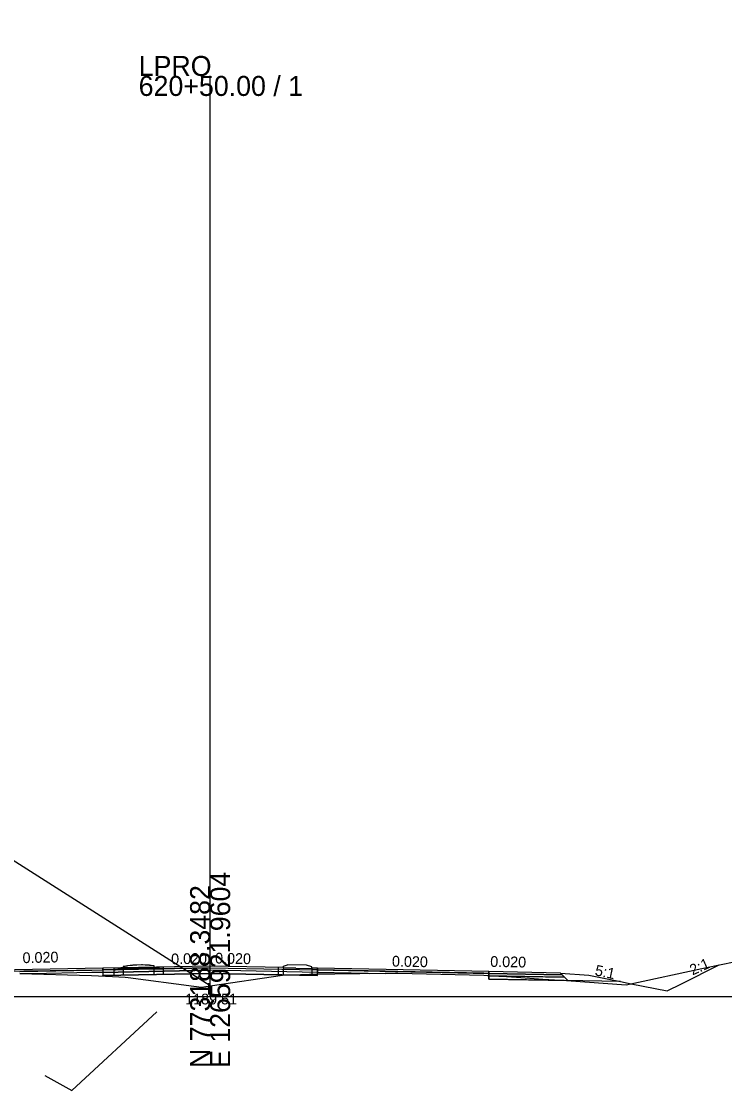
# Model space of a CAD drawing. Extents: x -3833 to 1267678, y -522 to 773248.
# Drawn here: x 3123.6 to 3222, y 1486.8 to 1636.6 of the extents above; entities that cross this region are included whole.
import ezdxf

# ---------------------------------------------------------------- set-up
doc = ezdxf.new("R2010")
doc.units = 0
for name, color, linetype in [('Exist Cross Section Cell', 7, 'Continuous'), ('Exist XS Center Line Elevation Label', 7, 'Continuous'), ('Exist XS Ground Line', 7, 'Continuous'), ('Prop CMT DNC', 7, 'Continuous'), ('Prop CMT Pvmt Course 1', 7, 'Continuous'), ('Prop CMT Pvmt Course 2', 7, 'Continuous'), ('Prop CMT Pvmt Course 3', 7, 'Continuous'), ('Prop CMT Pvmt Course 4', 7, 'Continuous'), ('Prop CMT Shld Paved Course 1', 7, 'Continuous'), ('Prop CMT Shld Paved Course 2', 7, 'Continuous'), ('Prop CMT Shld Paved Course 4', 7, 'Continuous'), ('Prop CMT Slope Grass', 7, 'Continuous'), ('Prop CMT Subgrade Earthwork', 7, 'Continuous'), ('Prop Conc Curb and Gutter', 7, 'Continuous'), ('Prop Conc Island Cover', 7, 'Continuous'), ('Prop Corridor Mesh Bottom', 7, 'Continuous'), ('Prop XS Ditch Slope Text', 7, 'Continuous'), ('Prop XS Finish Grade', 7, 'Continuous'), ('Prop XS SE Text', 7, 'Continuous'), ('Scratch_Level_1', 7, 'Continuous'), ('Scratch_Level_5', 7, 'Continuous')]:
    doc.layers.add(name, color=color, linetype=linetype)

msp = doc.modelspace()

# ---------------------------------------------------------------- linework, layer by layer
at = {"layer": 'Exist Cross Section Cell'}
for p, q in [((3150, 1500), (3150, 1628.93)), ((3000, 1500), (3150, 1500)), ((3150, 1500), (3300, 1500))]:
    msp.add_line(p, q, dxfattribs=at)
at = {"layer": 'Exist XS Ground Line'}
for p, q in [((3219.46, 1504.07), (3230.76, 1506.43)), ((3208.23, 1501.64), (3219.46, 1504.07)), ((3123.36, 1503.25), (3133.42, 1502.93)), ((3133.42, 1502.93), (3136.33, 1502.83)), ((3136.33, 1502.83), (3138.13, 1502.7)), ((3138.13, 1502.7), (3138.55, 1502.67)), ((3138.55, 1502.67), (3147.7, 1501.47)), ((3150, 1501.51), (3160.12, 1503)), ((3160.12, 1503), (3163.88, 1503.14)), ((3163.88, 1503.14), (3174.5, 1503.28)), ((3174.5, 1503.28), (3175.34, 1503.28)), ((3175.34, 1503.28), (3176.26, 1503.26)), ((3176.26, 1503.26), (3188.3, 1502.98)), ((3188.3, 1502.98), (3189.31, 1502.92)), ((3189.31, 1502.92), (3191.48, 1502.8)), ((3191.48, 1502.8), (3192.86, 1502.7)), ((3192.86, 1502.7), (3196.56, 1502.46)), ((3196.56, 1502.46), (3199.86, 1502.25)), ((3199.86, 1502.25), (3208.23, 1501.64)), ((3147.7, 1501.47), (3148.8, 1501.3)), ((3148.8, 1501.3), (3149.41, 1501.43)), ((3149.41, 1501.43), (3150, 1501.51))]:
    msp.add_line(p, q, dxfattribs=at)
at = {"layer": 'Prop CMT Pvmt Course 1'}
for p, q in [((3135, 1503.98), (3105, 1503.38)), ((3111.07, 1503.42), (3135, 1503.73)), ((3135, 1503.73), (3135, 1503.98)), ((3135, 1503.73), (3135, 1503.73)), ((3136.56, 1504), (3136.56, 1504.01)), ((3136.56, 1504.01), (3136.59, 1504.01)), ((3136.56, 1503.76), (3136.56, 1504)), ((3136.59, 1503.76), (3136.56, 1503.76)), ((3136.59, 1504.01), (3136.59, 1504.01)), ((3136.59, 1504.01), (3136.75, 1504.01)), ((3136.75, 1503.76), (3136.59, 1503.76)), ((3136.59, 1503.76), (3136.59, 1503.76)), ((3136.75, 1504.01), (3136.75, 1504.01)), ((3136.75, 1504.01), (3136.76, 1504.01)), ((3136.76, 1503.76), (3136.75, 1503.76)), ((3136.75, 1503.76), (3136.75, 1503.76)), ((3136.76, 1504.01), (3137.07, 1504.02)), ((3137.07, 1503.77), (3136.76, 1503.76)), ((3137.07, 1504.02), (3137.27, 1504.02)), ((3137.27, 1503.77), (3137.07, 1503.77)), ((3137.27, 1504.02), (3137.52, 1504.02)), ((3137.52, 1503.77), (3137.27, 1503.77)), ((3137.52, 1504.02), (3137.82, 1504.02)), ((3137.82, 1503.77), (3137.52, 1503.77)), ((3137.82, 1504.02), (3137.82, 1503.88)), ((3137.82, 1503.88), (3137.82, 1503.77)), ((3142.19, 1503.98), (3142.19, 1504.13)), ((3142.19, 1504.13), (3142.52, 1504.13)), ((3142.19, 1503.88), (3142.19, 1503.98)), ((3142.52, 1503.88), (3142.19, 1503.88)), ((3142.52, 1504.13), (3142.65, 1504.14)), ((3142.65, 1503.89), (3142.52, 1503.88)), ((3142.65, 1504.14), (3142.9, 1504.14)), ((3142.9, 1503.89), (3142.65, 1503.89)), ((3142.9, 1504.14), (3143.34, 1504.15)), ((3143.34, 1503.9), (3142.9, 1503.89)), ((3143.34, 1504.15), (3143.38, 1504.15)), ((3143.38, 1503.9), (3143.34, 1503.9)), ((3143.38, 1504.15), (3143.44, 1504.15)), ((3143.44, 1503.9), (3143.38, 1503.9)), ((3143.44, 1504.15), (3143.44, 1504.13)), ((3143.44, 1504.13), (3143.44, 1503.9)), ((3159.5, 1504.09), (3159.5, 1504.09)), ((3159.5, 1504.09), (3159.5, 1503.84)), ((3159.5, 1503.84), (3159.5, 1503.84)), ((3159.5, 1503.84), (3159.5, 1503.84)), ((3160.25, 1503.85), (3160.25, 1504.1)), ((3160.25, 1503.85), (3160.25, 1503.85)), ((3165, 1503.98), (3164.25, 1503.99)), ((3164.25, 1503.99), (3164.25, 1503.74)), ((3164.25, 1503.74), (3164.25, 1503.74)), ((3189, 1503.5), (3165, 1503.98)), ((3165, 1503.98), (3165, 1503.73)), ((3165, 1503.73), (3165, 1503.98)), ((3165, 1503.98), (3165, 1503.98)), ((3165, 1503.73), (3165, 1503.73)), ((3165, 1503.73), (3189, 1503.25)), ((3165, 1503.73), (3165, 1503.73)), ((3165, 1503.73), (3165, 1503.73)), ((3189, 1503.25), (3189, 1503.5)), ((3189, 1503.5), (3189, 1503.5)), ((3189, 1503.25), (3189, 1503.25)), ((3189, 1503.25), (3189, 1503.25))]:
    msp.add_line(p, q, dxfattribs=at)
at = {"layer": 'Prop CMT Pvmt Course 2'}
for p, q in [((3150, 1504.03), (3135, 1503.73)), ((3135, 1503.73), (3135, 1503.73)), ((3135, 1503.73), (3135, 1503.4)), ((3135, 1503.39), (3150, 1503.7)), ((3136.56, 1503.75), (3136.56, 1503.76)), ((3136.56, 1503.76), (3136.59, 1503.76)), ((3136.56, 1503.51), (3136.56, 1503.75)), ((3136.59, 1503.76), (3136.59, 1503.76)), ((3136.59, 1503.76), (3136.75, 1503.76)), ((3136.75, 1503.76), (3136.75, 1503.76)), ((3136.75, 1503.76), (3136.76, 1503.76)), ((3136.76, 1503.76), (3137.07, 1503.77)), ((3137.07, 1503.77), (3137.27, 1503.77)), ((3137.27, 1503.77), (3137.52, 1503.77)), ((3137.52, 1503.77), (3137.82, 1503.77)), ((3137.82, 1503.77), (3137.82, 1503.63)), ((3137.82, 1503.63), (3137.82, 1503.52)), ((3142.19, 1503.73), (3142.19, 1503.88)), ((3142.19, 1503.88), (3142.52, 1503.88)), ((3142.19, 1503.63), (3142.19, 1503.73)), ((3142.52, 1503.88), (3142.65, 1503.89)), ((3142.65, 1503.89), (3142.9, 1503.89)), ((3142.9, 1503.89), (3143.34, 1503.9)), ((3143.34, 1503.9), (3143.38, 1503.9)), ((3143.38, 1503.9), (3143.44, 1503.9)), ((3143.44, 1503.9), (3143.44, 1503.88)), ((3143.44, 1503.88), (3143.44, 1503.65)), ((3159.5, 1503.84), (3159.5, 1503.84)), ((3159.5, 1503.84), (3159.5, 1503.59)), ((3159.5, 1503.59), (3159.5, 1503.59)), ((3159.5, 1503.59), (3159.5, 1503.59)), ((3160.25, 1503.6), (3160.25, 1503.85)), ((3160.25, 1503.6), (3160.25, 1503.6)), ((3165, 1503.73), (3164.25, 1503.74)), ((3164.25, 1503.74), (3164.25, 1503.49)), ((3164.25, 1503.49), (3164.25, 1503.49)), ((3165, 1503.39), (3165, 1503.73)), ((3165, 1503.73), (3165, 1503.73)), ((3165, 1503.48), (3165, 1503.73)), ((3165, 1503.73), (3165, 1503.73)), ((3165, 1503.48), (3165, 1503.48)), ((3165, 1503.48), (3165, 1503.48)), ((3135, 1503.4), (3135, 1503.4)), ((3135, 1503.4), (3135, 1503.39)), ((3135, 1503.39), (3135, 1503.39)), ((3135, 1503.39), (3135, 1503.39)), ((3165, 1503.39), (3165, 1503.39)), ((3165, 1503.39), (3165, 1503.39)), ((3165, 1503.39), (3165, 1503.39))]:
    msp.add_line(p, q, dxfattribs=at)
at = {"layer": 'Prop CMT Pvmt Course 3'}
for p, q in [((3136.56, 1503.5), (3136.56, 1503.51)), ((3136.56, 1503.13), (3136.56, 1503.5)), ((3137.82, 1503.52), (3137.82, 1503.31)), ((3142.19, 1503.41), (3142.19, 1503.63)), ((3143.44, 1503.65), (3143.44, 1503.62)), ((3143.44, 1503.62), (3143.44, 1503.27)), ((3159.5, 1503.59), (3159.5, 1503.59)), ((3159.5, 1503.59), (3159.5, 1503.05)), ((3160.25, 1503.03), (3160.25, 1503.6)), ((3164.25, 1503.49), (3164.25, 1502.95)), ((3165, 1502.94), (3165, 1503.48)), ((3165, 1503.48), (3165, 1503.48)), ((3137.82, 1503.31), (3137.82, 1503.15)), ((3142.19, 1503.25), (3142.19, 1503.41)), ((3159.5, 1503.21), (3159.5, 1503.21)), ((3159.5, 1503.21), (3159.5, 1503.21)), ((3160.25, 1503.23), (3160.25, 1503.23)), ((3164.25, 1503.12), (3164.25, 1503.12)), ((3174.47, 1503.2), (3164.99, 1503.39)), ((3165, 1503.1), (3165, 1503.1)), ((3165, 1503.1), (3165, 1503.1))]:
    msp.add_line(p, q, dxfattribs=at)
at = {"layer": 'Prop CMT Pvmt Course 4'}
for p, q in [((3150, 1503.7), (3135, 1503.39)), ((3165, 1503.39), (3150, 1503.7)), ((3135, 1503.39), (3135, 1503.4)), ((3135, 1503.4), (3135, 1502.88)), ((3135, 1503.39), (3135, 1503.39)), ((3135, 1503.39), (3135, 1503.39)), ((3135, 1502.94), (3150.01, 1503.24)), ((3136.56, 1503.12), (3136.56, 1503.13)), ((3136.56, 1502.97), (3136.56, 1503.12)), ((3137.82, 1503.15), (3137.82, 1502.99)), ((3142.19, 1503.08), (3142.19, 1503.25)), ((3143.44, 1503.27), (3143.44, 1503.23)), ((3143.44, 1503.23), (3143.44, 1503.11)), ((3150, 1503.24), (3165, 1502.94)), ((3159.5, 1503.21), (3159.5, 1503.21)), ((3165, 1502.94), (3165, 1503.39)), ((3165, 1503.39), (3165, 1503.39)), ((3165, 1503.39), (3165, 1503.39)), ((3165, 1502.94), (3165, 1503.1)), ((3165, 1503.1), (3165, 1503.1))]:
    msp.add_line(p, q, dxfattribs=at)
at = {"layer": 'Prop CMT Shld Paved Course 1'}
for p, q in [((3150, 1504.28), (3135, 1503.98)), ((3135, 1503.73), (3150, 1504.03)), ((3135, 1503.98), (3135, 1503.98)), ((3135, 1503.98), (3135, 1503.73)), ((3135, 1503.73), (3135, 1503.73)), ((3135, 1503.73), (3135, 1503.73)), ((3160.25, 1504.07), (3150, 1504.28)), ((3150, 1504.03), (3165, 1503.73)), ((3165, 1503.98), (3164.25, 1503.99)), ((3165, 1503.73), (3165, 1503.98)), ((3165, 1503.98), (3165, 1503.98)), ((3165, 1503.73), (3165, 1503.73)), ((3165, 1503.73), (3165, 1503.73)), ((3189, 1503.5), (3189, 1503.25)), ((3199, 1503.3), (3189, 1503.5)), ((3189, 1503.25), (3199.26, 1503.04)), ((3199.26, 1503.04), (3199, 1503.3))]:
    msp.add_line(p, q, dxfattribs=at)
at = {"layer": 'Prop CMT Shld Paved Course 2'}
for p, q in [((3123.35, 1503.49), (3133.43, 1503.7)), ((3133.43, 1503.7), (3135, 1503.73)), ((3133.43, 1503.7), (3133.43, 1503.7)), ((3135, 1503.73), (3135, 1503.73)), ((3135, 1503.73), (3135, 1503.39)), ((3174.48, 1503.54), (3165, 1503.73)), ((3165, 1503.73), (3165, 1503.39)), ((3175.34, 1503.52), (3174.48, 1503.54)), ((3174.48, 1503.54), (3174.48, 1503.54)), ((3176.26, 1503.5), (3175.34, 1503.52)), ((3175.34, 1503.52), (3175.34, 1503.52)), ((3175.34, 1503.52), (3175.34, 1503.52)), ((3188.29, 1503.26), (3176.26, 1503.5)), ((3176.26, 1503.5), (3176.26, 1503.5)), ((3125.01, 1503.19), (3123.35, 1503.25)), ((3133.43, 1503.36), (3125.01, 1503.19)), ((3125.01, 1503.19), (3125.01, 1503.19)), ((3135, 1503.39), (3133.43, 1503.36)), ((3133.43, 1503.36), (3133.43, 1503.36)), ((3135, 1503.39), (3135, 1503.39)), ((3135, 1503.39), (3135, 1503.39)), ((3165, 1503.39), (3165, 1503.39)), ((3165, 1503.39), (3165, 1503.39)), ((3165, 1503.39), (3172.33, 1503.25)), ((3172.33, 1503.25), (3174.48, 1503.28)), ((3174.48, 1503.28), (3174.48, 1503.28)), ((3174.48, 1503.28), (3175.34, 1503.28)), ((3175.34, 1503.28), (3175.34, 1503.28)), ((3175.34, 1503.28), (3175.34, 1503.28)), ((3175.34, 1503.28), (3176.26, 1503.26)), ((3176.26, 1503.26), (3176.26, 1503.26)), ((3176.26, 1503.26), (3188.29, 1502.98)), ((3189, 1503.25), (3188.29, 1503.26)), ((3188.29, 1503.26), (3188.29, 1503.26)), ((3188.29, 1502.98), (3188.29, 1502.98)), ((3188.29, 1502.98), (3189, 1502.94)), ((3189, 1502.94), (3189, 1503.25)), ((3189, 1503.25), (3189, 1503.25)), ((3189, 1503.25), (3189, 1502.92)), ((3199.26, 1503.04), (3189, 1503.25)), ((3189, 1502.94), (3189, 1502.94)), ((3189, 1502.94), (3189, 1502.94)), ((3189, 1502.92), (3199.59, 1502.71)), ((3199.59, 1502.71), (3199.26, 1503.04))]:
    msp.add_line(p, q, dxfattribs=at)
at = {"layer": 'Prop CMT Shld Paved Course 4'}
for p, q in [((3189, 1502.92), (3189, 1502.46)), ((3199.09, 1502.72), (3189, 1502.92)), ((3189, 1502.46), (3200.06, 1502.24)), ((3199.59, 1502.71), (3199.09, 1502.72)), ((3200.06, 1502.24), (3199.59, 1502.71))]:
    msp.add_line(p, q, dxfattribs=at)
at = {"layer": 'Prop CMT Slope Grass'}
for p, q in [((3199, 1503.3), (3203, 1502.98)), ((3203, 1502.98), (3207.44, 1502.09))]:
    msp.add_line(p, q, dxfattribs=at)
at = {"layer": 'Prop CMT Subgrade Earthwork'}
for p, q in [((3150, 1503.24), (3135, 1502.94)), ((3135, 1502.88), (3135, 1502.94)), ((3165, 1502.94), (3150, 1503.24)), ((3165, 1502.94), (3165, 1503.15)), ((3189, 1502.46), (3189, 1502.94)), ((3207.44, 1502.09), (3189, 1502.46))]:
    msp.add_line(p, q, dxfattribs=at)
at = {"layer": 'Prop Conc Curb and Gutter'}
for p, q in [((3137.83, 1504.1), (3137.82, 1504.02)), ((3137.82, 1503.95), (3137.82, 1504.02)), ((3137.82, 1503.9), (3137.82, 1503.95)), ((3138.15, 1503.9), (3137.82, 1503.9)), ((3137.84, 1504.19), (3137.83, 1504.1)), ((3138.08, 1504.23), (3137.84, 1504.19)), ((3138.2, 1504.26), (3138.08, 1504.23)), ((3138.2, 1503.9), (3138.15, 1503.9)), ((3138.24, 1504.26), (3138.2, 1504.26)), ((3138.25, 1503.9), (3138.2, 1503.9)), ((3138.25, 1504.26), (3138.24, 1504.26)), ((3138.32, 1504.27), (3138.25, 1504.26)), ((3138.34, 1503.9), (3138.25, 1503.9)), ((3138.25, 1503.9), (3138.25, 1503.9)), ((3138.35, 1504.28), (3138.32, 1504.27)), ((3138.35, 1503.9), (3138.34, 1503.9)), ((3138.44, 1504.29), (3138.35, 1504.28)), ((3138.48, 1503.9), (3138.35, 1503.9)), ((3138.49, 1504.3), (3138.44, 1504.29)), ((3138.49, 1503.9), (3138.48, 1503.9)), ((3138.8, 1504.33), (3138.49, 1504.3)), ((3138.98, 1503.91), (3138.49, 1503.9)), ((3139.08, 1504.37), (3138.8, 1504.33)), ((3139.08, 1503.91), (3138.98, 1503.91)), ((3139.19, 1504.38), (3139.08, 1504.37)), ((3139.32, 1503.91), (3139.08, 1503.91)), ((3139.38, 1504.39), (3139.19, 1504.38)), ((3139.38, 1503.92), (3139.32, 1503.91)), ((3139.41, 1504.4), (3139.38, 1504.39)), ((3139.45, 1503.92), (3139.38, 1503.92)), ((3139.47, 1504.4), (3139.41, 1504.4)), ((3139.47, 1503.92), (3139.45, 1503.92)), ((3139.72, 1504.41), (3139.47, 1504.4)), ((3139.68, 1503.93), (3139.47, 1503.92)), ((3140.39, 1503.94), (3139.68, 1503.93)), ((3140.39, 1504.43), (3139.72, 1504.41)), ((3140.41, 1504.43), (3140.39, 1504.43)), ((3140.39, 1504.43), (3140.39, 1504.43)), ((3140.41, 1503.94), (3140.39, 1503.94)), ((3140.39, 1503.94), (3140.39, 1503.94)), ((3140.55, 1504.43), (3140.41, 1504.43)), ((3140.52, 1503.95), (3140.41, 1503.94)), ((3140.89, 1503.96), (3140.52, 1503.95)), ((3140.89, 1504.42), (3140.55, 1504.43)), ((3141.1, 1504.4), (3140.89, 1504.42)), ((3140.97, 1503.96), (3140.89, 1503.96)), ((3141.35, 1503.97), (3140.97, 1503.96)), ((3141.35, 1504.39), (3141.1, 1504.4)), ((3141.43, 1504.38), (3141.35, 1504.39)), ((3141.37, 1503.98), (3141.35, 1503.97)), ((3141.48, 1503.98), (3141.37, 1503.98)), ((3141.48, 1504.38), (3141.43, 1504.38)), ((3141.5, 1504.38), (3141.48, 1504.38)), ((3141.51, 1503.98), (3141.48, 1503.98)), ((3141.48, 1503.98), (3141.48, 1503.98)), ((3141.51, 1504.37), (3141.5, 1504.38)), ((3141.69, 1504.36), (3141.51, 1504.37)), ((3141.53, 1503.98), (3141.51, 1503.98)), ((3141.76, 1503.99), (3141.53, 1503.98)), ((3141.76, 1504.35), (3141.69, 1504.36)), ((3142.17, 1504.29), (3141.76, 1504.35)), ((3141.8, 1503.99), (3141.76, 1503.99)), ((3142.19, 1504), (3141.8, 1503.99)), ((3142.18, 1504.2), (3142.17, 1504.29)), ((3142.19, 1504.13), (3142.18, 1504.2)), ((3142.19, 1504.13), (3142.19, 1504.05)), ((3142.19, 1504.05), (3142.19, 1504)), ((3160.25, 1504.1), (3160.26, 1504.27)), ((3160.25, 1503.98), (3160.25, 1504.1)), ((3160.25, 1504.1), (3160.25, 1504.1)), ((3162.01, 1503.98), (3160.25, 1503.98)), ((3160.25, 1503.98), (3160.25, 1503.98)), ((3160.26, 1504.27), (3160.84, 1504.46)), ((3160.26, 1504.27), (3160.26, 1504.27)), ((3163.49, 1504.41), (3160.84, 1504.46)), ((3162.01, 1503.98), (3162.01, 1503.98)), ((3162.01, 1503.98), (3162.01, 1503.98)), ((3162.01, 1503.98), (3164.25, 1503.93)), ((3164.24, 1504.16), (3163.49, 1504.41)), ((3163.49, 1504.41), (3163.49, 1504.41)), ((3164.25, 1503.93), (3164.24, 1504.16)), ((3164.24, 1504.16), (3164.24, 1504.16)), ((3164.25, 1503.99), (3164.25, 1503.99)), ((3164.25, 1503.99), (3164.25, 1503.99)), ((3164.25, 1503.99), (3164.25, 1503.99)), ((3164.25, 1503.87), (3164.25, 1503.87)), ((3164.25, 1503.87), (3164.25, 1503.87))]:
    msp.add_line(p, q, dxfattribs=at)
at = {"layer": 'Prop Conc Island Cover'}
msp.add_line((3162.49, 1504.43), (3162.49, 1504.43), dxfattribs=at)
at = {"layer": 'Prop Corridor Mesh Bottom'}
for p, q in [((3135, 1503.98), (3135, 1503.73)), ((3165, 1503.98), (3165, 1503.73)), ((3189, 1503.5), (3189, 1503.25))]:
    msp.add_line(p, q, dxfattribs=at)
at = {"layer": 'Prop XS Finish Grade'}
for p, q in [((3207.44, 1502.09), (3208.93, 1501.79)), ((3208.93, 1501.79), (3213.94, 1500.79))]:
    msp.add_line(p, q, dxfattribs=at)
msp.add_lwpolyline([(3213.94, 1500.79), (3215.94, 1501.79), (3221.24, 1504.44)], dxfattribs=at)
at = {"layer": 'Scratch_Level_1'}
msp.add_line((3150, 1501.51), (2937.75, 1636.57), dxfattribs=at)
at = {"layer": 'Scratch_Level_5'}
for p, q in [((3130.66, 1486.83), (3142.52, 1497.85)), ((3126.88, 1488.93), (3130.66, 1486.83))]:
    msp.add_line(p, q, dxfattribs=at)

# ---------------------------------------------------------------- texts
at = {"layer": 'Exist Cross Section Cell'}
for s, p in [('LPRO', (3140, 1628.93)), ('620+50.00 / 1', (3140, 1626.13))]:
    msp.add_text(s, height=2.8, dxfattribs=at).set_placement(p)
for s, p in [('E 1265921.9604', (3152.8, 1490)), ('N 773188.3482', (3150, 1490))]:
    msp.add_text(s, height=2.8, rotation=90, dxfattribs=at).set_placement(p)
at = {"layer": 'Exist XS Center Line Elevation Label'}
msp.add_text('1189.51', height=1.5, dxfattribs=at).set_placement((3146.51, 1498.9))
at = {"layer": 'Prop CMT DNC'}
for p in [(3135, 1503.98), (3135, 1503.98), (3150, 1504.28), (3165, 1503.98), (3165, 1503.98), (3189, 1503.5), (3189, 1503.5), (3199, 1503.3)]:
    msp.add_text('X', height=0.00025, dxfattribs=at).set_placement(p)
at = {"layer": 'Prop XS Ditch Slope Text'}
for s, rotation, p in [('2:1', 23.8989, (3217.5, 1502.95)), ('5:1', 348.3072, (3203.75, 1502.99))]:
    msp.add_text(s, height=1.5, rotation=rotation, dxfattribs=at).set_placement(p)
at = {"layer": 'Prop XS SE Text'}
for rotation, p in [(1.299, (3123.77, 1504.68)), (1.26, (3144.56, 1504.51)), (358.8542, (3150.68, 1504.64)), (358.8542, (3175.43, 1504.21)), (358.8542, (3189.18, 1504.17))]:
    msp.add_text('0.020', height=1.5, rotation=rotation, dxfattribs=at).set_placement(p)

doc.saveas('drawing.dxf')
